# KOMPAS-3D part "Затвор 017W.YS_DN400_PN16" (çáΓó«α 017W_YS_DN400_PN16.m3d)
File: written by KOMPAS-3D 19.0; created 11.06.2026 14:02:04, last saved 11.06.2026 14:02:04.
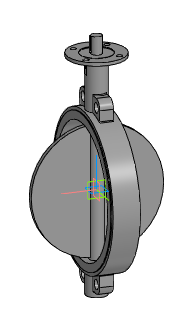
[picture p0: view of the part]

Document properties: Автор: Евгений; Полное имя файла: Z:\3.Личные\kachalov\001_3d для проектировщиков\x.x Тип 017W.Y(S) Затвор дисковый поворотный межфланцевый\_stp_Затвор 017W.YS_DN32-DN1200\Затвор 017W_YS_DN400_PN16.m3d

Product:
- Part/product: Затвор 017W.YS_DN400_PN16

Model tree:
1. Операция без истории:1  (labels: Затвор 017W.YS_DN400_PN16)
